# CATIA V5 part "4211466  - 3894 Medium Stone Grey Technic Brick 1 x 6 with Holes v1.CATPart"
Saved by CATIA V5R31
Part number: 1x6
Definition: 4211466  - 3894 Medium Stone Grey Technic Brick 1 x 6 with Holes v1
Nomenclature: 4211466  - 3894 Medium Stone Grey Technic Brick 1 x 6 with Holes v1
Source: Unknown
Bounding box of the stored display mesh (mm): x -4 to 44, y 0 to 11.2, z -4 to 4
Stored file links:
  C:\Users\super\Desktop\LEGO\TFG-2621\TFG_02621_anejos\4211466  - 3894 Medium Stone Grey Technic Brick 1 x 6 with Holes v1.CATPart
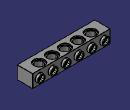
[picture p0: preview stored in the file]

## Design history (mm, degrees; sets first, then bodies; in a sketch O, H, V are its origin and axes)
AxisSystem1: origin (0, 0, 0), X (1, 0, 0), Y (0, 1, 0), Z (0, 0, 1)
Body1 "Body1" (main body)
  Solid1: solid without history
